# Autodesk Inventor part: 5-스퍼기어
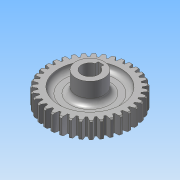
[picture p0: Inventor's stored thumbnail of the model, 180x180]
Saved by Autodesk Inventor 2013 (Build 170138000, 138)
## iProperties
Created: 2013-08
Part Number: 5-스퍼기어
Material: 강
Document SubType Name: Modeling
Designer: 한국산업디자인학원
Categories: <?xml version="1.0" encoding="UTF-16"?> <MemberInstance><Categories><FamilyTemplate><FamilyTemplateParameter ValueType="xs:double" Id="1" ObjectReferenceKey="da
Density: 1 g/cm^3
CustomPartVersion: 1
Author: 한국산업디자인학원
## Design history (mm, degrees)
sketch "Sketch1"
  geometry: C1 r 37 at (0, 0)
  constraints: 1 centre point
  dimensions: "d0" = 74 diameter of C1 (= da_da)
extrude "Extrusion1" new body sketch "Sketch1" distance "d1" = 15 (= da_b); taper "d2" = 0 deg
chamfer "모따기1" distance "d49" = 1; stored, may be unused: second distance "d50" = 2, angle "d51" = 45 deg
node "작업 평면11"
sketch "스케치3"
  geometry: C1 r 12.5 at (0, 0); 1 further point
  constraints: 1 centre point, 1 coincident
  dimensions: "d53" = 25 diameter of C1
extrude "돌출2" join sketch "스케치3" distance "d55" = 31; taper "d56" = 0 deg
sketch "스케치4"
  geometry: L1 (-2.5, 7.071)-(-2.5, 9.8); L2 (-2.5, 9.8)-(2.5, 9.8); L3 (2.5, 9.8)-(2.5, 7.071); C1 r 12.5 at (0, 0) reference; A1 r 7.5 centre (0, 0) between (-2.5, 7.071) and (2.5, 7.071)
  constraints: 6 end point, 2 parallel, 2 point on circle, 1 centre point, 1 coincident, 1 perpendicular, 1 vertical
  dimensions: "d57" = 15 diameter of A1; "d59" = 5 distance of L1.end L2.end; "d60" = 17.3 dimension on A1 L2
extrude "돌출3" cut sketch "스케치4" distance "d61" = 31; taper "d62" = 0 deg
workplane "Work Plane2"
feature "피치 지름" dims "d4" = 10, "d5" = 0
workplane "Work Plane8"
workplane "Work Plane9"
feature "스퍼 기어" dims "da_b" = 15, "da_d" = 70, "da_aw" = 70, "da_da" = 74, "da_df" = 65, "da_dw" = 70, angle "da_beta" = 0 deg, "da_lefttooth" = 0, "da_righttooth" = 0
sketch "스케치5"
  geometry: C1 r 12.5 at (0, 0) reference; C2 r 27.5 at (0, 0); C3 r 12.5 at (0, 0)
  constraints: 2 centre point, 2 coincident
  dimensions: "d63" = 55 diameter of C2; "d65" = 25 diameter of C3
extrude "돌출4" cut sketch "스케치5" distance "d66" = 5; taper "d67" = 0 deg
sketch "스케치7"
  geometry: C1 r 12.5 at (0, 0) reference; C2 r 27.5 at (0, 0) reference; C3 r 12.5 at (0, 0) reference
extrude "돌출5" cut sketch "스케치7" distance "d68" = 5; taper "d69" = 0 deg
fillet "모깎기1" dims "d70" = 5
body "Solid1"
sketch "Sketch2"
  geometry: C1 r 37 at (0, 0) reference; C2 r 35 at (0, 0)
  constraints: 1 centre point, 1 coincident
  dimensions: "d3" = 70 diameter of C2 (= da_dw)
body "Srf1"
other parameters: "d17" = 0, "d34" = 0.8976 (computed from da_z), "d39" = 0, "d41" = 0, "d47" = 0, "d48" = 0, "d52" = 3
